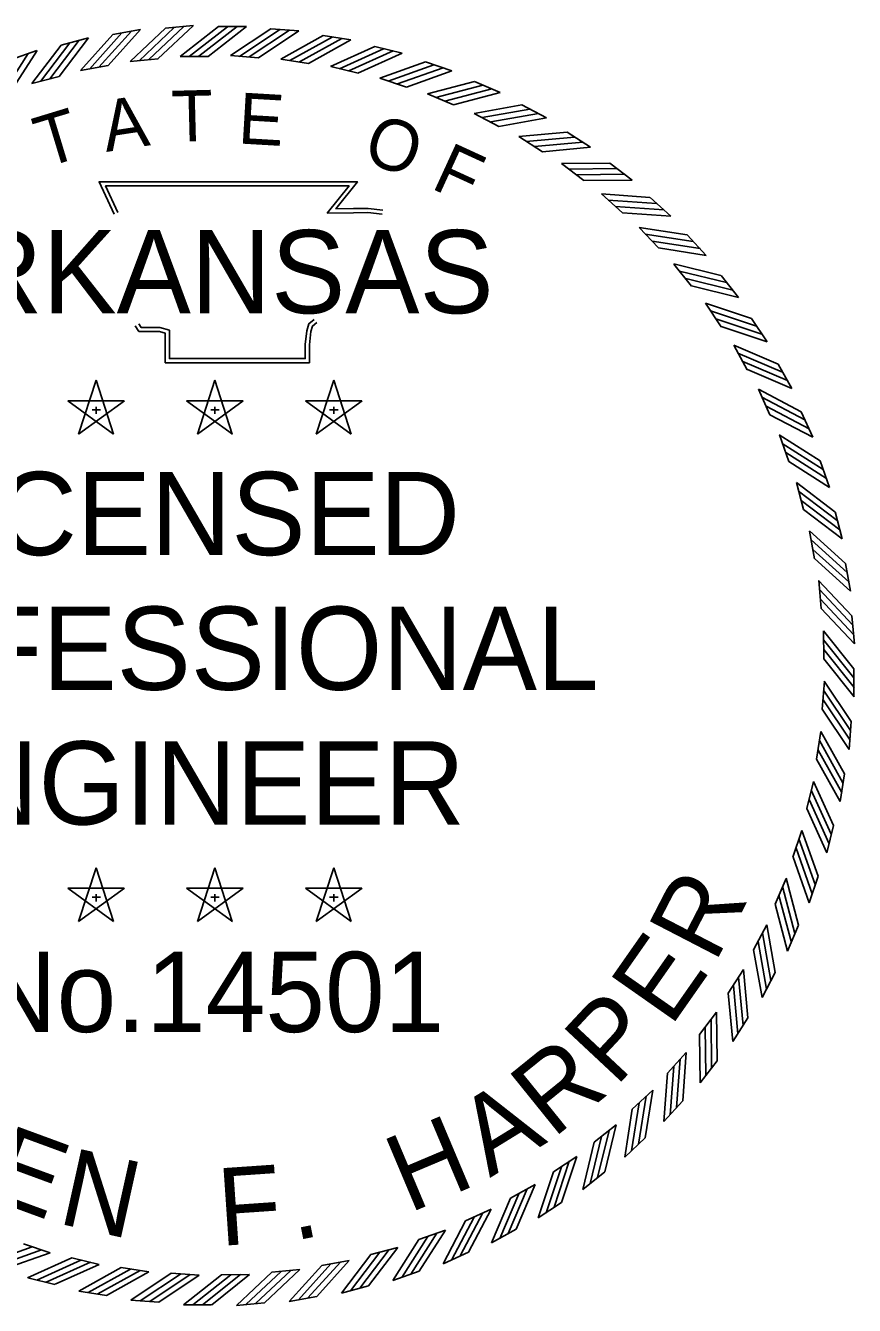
# Model space of a CAD drawing. Extents: x 16 to 1228740, y 11 to 152440.
# Drawn here: x 17.7445 to 17.8561, y 10.8148 to 10.987 of the extents above; entities that cross this region are included whole.
import ezdxf

# ---------------------------------------------------------------- set-up
doc = ezdxf.new("R2010")
doc.units = 0
doc.layers.add('STAMP_FRED', color=7, linetype='Continuous')

msp = doc.modelspace()

# ---------------------------------------------------------------- linework, layer by layer
at = {"layer": 'STAMP_FRED'}
for p, q in [((17.75631, 10.98579), (17.76003, 10.98645)), ((17.76337, 10.98663), (17.76712, 10.98698)), ((17.77051, 10.98684), (17.77428, 10.98684)), ((17.77757, 10.98656), (17.78133, 10.98629)), ((17.74935, 10.98437), (17.753, 10.98533)), ((17.78462, 10.98565), (17.78834, 10.98506)), ((17.74253, 10.98238), (17.74608, 10.98363)), ((17.76536, 10.98283), (17.76914, 10.98283)), ((17.77214, 10.98294), (17.77591, 10.98266)), ((17.79156, 10.98415), (17.79523, 10.98326)), ((17.75194, 10.98095), (17.75566, 10.9816)), ((17.75861, 10.98217), (17.76238, 10.98251)), ((17.77891, 10.98248), (17.78264, 10.9819)), ((17.78562, 10.98147), (17.78929, 10.98058)), ((17.79836, 10.98209), (17.80194, 10.9809)), ((17.7454, 10.97918), (17.74905, 10.98014)), ((17.79222, 10.97991), (17.7958, 10.97872)), ((17.80497, 10.97947), (17.80844, 10.97799)), ((17.79866, 10.97781), (17.80214, 10.97632)), ((17.81134, 10.97632), (17.81467, 10.97456)), ((17.80492, 10.97518), (17.80825, 10.97341)), ((17.81742, 10.97265), (17.8206, 10.97062)), ((17.81093, 10.97205), (17.81411, 10.97001)), ((17.81666, 10.96843), (17.81967, 10.96613)), ((17.82319, 10.96849), (17.82618, 10.96621)), ((17.82208, 10.96435), (17.82488, 10.96181)), ((17.82859, 10.96387), (17.83138, 10.96135)), ((17.82714, 10.95983), (17.82972, 10.95707)), ((17.83359, 10.95882), (17.83616, 10.95607)), ((17.83181, 10.95491), (17.83416, 10.95195)), ((17.83815, 10.95338), (17.84049, 10.95042)), ((17.83606, 10.94963), (17.83815, 10.94648)), ((17.84225, 10.94757), (17.84434, 10.94444)), ((17.83986, 10.94401), (17.84168, 10.9407)), ((17.84586, 10.94145), (17.84768, 10.93815)), ((17.75403, 10.93928), (17.75168, 10.93204)), ((17.75638, 10.93205), (17.75404, 10.93929)), ((17.77002, 10.93928), (17.76767, 10.93204)), ((17.77237, 10.93205), (17.77003, 10.93929)), ((17.78602, 10.93928), (17.78366, 10.93204)), ((17.78836, 10.93205), (17.78602, 10.93929)), ((17.84318, 10.9381), (17.84473, 10.93465)), ((17.75784, 10.93652), (17.75023, 10.93653)), ((17.75023, 10.93652), (17.75638, 10.93204)), ((17.75168, 10.93205), (17.75785, 10.93652)), ((17.77383, 10.93652), (17.76622, 10.93653)), ((17.76622, 10.93652), (17.77238, 10.93204)), ((17.76767, 10.93205), (17.77384, 10.93652)), ((17.78982, 10.93652), (17.78221, 10.93653)), ((17.78221, 10.93652), (17.78837, 10.93204)), ((17.78367, 10.93205), (17.78983, 10.93652)), ((17.75349, 10.9353), (17.75462, 10.9353)), ((17.75404, 10.93571), (17.75404, 10.93475)), ((17.76948, 10.9353), (17.77061, 10.9353)), ((17.77003, 10.93571), (17.77003, 10.93475)), ((17.78547, 10.9353), (17.7866, 10.9353)), ((17.78602, 10.93571), (17.78602, 10.93475)), ((17.84894, 10.93505), (17.85049, 10.93161)), ((17.846, 10.93193), (17.84726, 10.92837)), ((17.85149, 10.92842), (17.85275, 10.92486)), ((17.8483, 10.92555), (17.84926, 10.92189)), ((17.85349, 10.92159), (17.85445, 10.91795)), ((17.85007, 10.919), (17.85072, 10.91528)), ((17.85491, 10.91463), (17.85556, 10.91092)), ((17.85129, 10.91233), (17.85163, 10.90857)), ((17.85575, 10.90758), (17.8561, 10.90382)), ((17.85195, 10.90558), (17.85199, 10.9018)), ((17.85601, 10.90047), (17.85604, 10.8967)), ((17.85206, 10.8988), (17.85178, 10.89503)), ((17.85568, 10.89338), (17.8554, 10.88962)), ((17.8516, 10.89203), (17.85102, 10.8883)), ((17.85477, 10.88633), (17.85418, 10.88261)), ((17.85059, 10.88533), (17.8497, 10.88166)), ((17.85327, 10.87938), (17.85238, 10.87572)), ((17.84903, 10.87873), (17.84783, 10.87514)), ((17.75403, 10.87372), (17.75168, 10.86648)), ((17.75638, 10.86648), (17.75404, 10.87372)), ((17.77002, 10.87372), (17.76767, 10.86648)), ((17.77237, 10.86648), (17.77003, 10.87372)), ((17.78602, 10.87372), (17.78366, 10.86648)), ((17.78836, 10.86648), (17.78602, 10.87372)), ((17.85121, 10.87258), (17.85002, 10.869)), ((17.75784, 10.87095), (17.75023, 10.87096)), ((17.75023, 10.87095), (17.75638, 10.86647)), ((17.75168, 10.86648), (17.75785, 10.87095)), ((17.77383, 10.87095), (17.76622, 10.87096)), ((17.76622, 10.87095), (17.77238, 10.86647)), ((17.76767, 10.86648), (17.77384, 10.87095)), ((17.78982, 10.87095), (17.78221, 10.87096)), ((17.78221, 10.87095), (17.78837, 10.86647)), ((17.78367, 10.86648), (17.78983, 10.87095)), ((17.84693, 10.87228), (17.84544, 10.86881)), ((17.75349, 10.86974), (17.75462, 10.86974)), ((17.75404, 10.87014), (17.75404, 10.86919)), ((17.76948, 10.86974), (17.77061, 10.86974)), ((17.77003, 10.87014), (17.77003, 10.86919)), ((17.78547, 10.86974), (17.7866, 10.86974)), ((17.78602, 10.87014), (17.78602, 10.86919)), ((17.8443, 10.86603), (17.84253, 10.86269)), ((17.84859, 10.86597), (17.84711, 10.86251)), ((17.84117, 10.86002), (17.83913, 10.85683)), ((17.84544, 10.85961), (17.84368, 10.85627)), ((17.83755, 10.85428), (17.83525, 10.85128)), ((17.84177, 10.85352), (17.83974, 10.85035)), ((17.83346, 10.84887), (17.83093, 10.84606)), ((17.83761, 10.84776), (17.83532, 10.84476)), ((17.82895, 10.8438), (17.82619, 10.84122)), ((17.83299, 10.84236), (17.83046, 10.83956)), ((17.82403, 10.83913), (17.82107, 10.83679)), ((17.82794, 10.83736), (17.82519, 10.83478)), ((17.81875, 10.83489), (17.8156, 10.83279)), ((17.82249, 10.83279), (17.81954, 10.83045)), ((17.81313, 10.83109), (17.80982, 10.82926)), ((17.80721, 10.82777), (17.80377, 10.82622)), ((17.81669, 10.82869), (17.81355, 10.8266)), ((17.80105, 10.82495), (17.79748, 10.82369)), ((17.81057, 10.82509), (17.80727, 10.82326)), ((17.74785, 10.82192), (17.74426, 10.82311)), ((17.79467, 10.82265), (17.79101, 10.82168)), ((17.75445, 10.82035), (17.75078, 10.82125)), ((17.78812, 10.82088), (17.7844, 10.82022)), ((17.80417, 10.822), (17.80073, 10.82045)), ((17.76115, 10.81934), (17.75742, 10.81993)), ((17.76792, 10.81889), (17.76415, 10.81917)), ((17.78145, 10.81966), (17.77769, 10.81931)), ((17.79753, 10.81945), (17.79398, 10.81819)), ((17.7485, 10.81767), (17.74484, 10.81857)), ((17.7747, 10.81899), (17.77092, 10.81896)), ((17.79071, 10.81746), (17.78707, 10.8165)), ((17.75545, 10.81618), (17.75172, 10.81677)), ((17.78375, 10.81604), (17.78004, 10.81538)), ((17.76249, 10.81526), (17.75873, 10.81554)), ((17.76959, 10.81493), (17.76582, 10.8149)), ((17.77669, 10.81519), (17.77294, 10.81485))]:
    msp.add_line(p, q, dxfattribs=at)
for points in [[(17.75314, 10.98114), (17.7575, 10.98599)], [(17.75442, 10.9814), (17.75879, 10.98624)], [(17.75566, 10.98161), (17.76003, 10.98645)], [(17.75861, 10.98216), (17.76336, 10.98663)], [(17.75982, 10.98226), (17.76457, 10.98673)], [(17.76112, 10.98241), (17.76587, 10.98688)], [(17.76237, 10.98252), (17.76713, 10.98698)], [(17.76536, 10.98283), (17.7705, 10.98684)], [(17.76657, 10.98282), (17.77172, 10.98683)], [(17.76788, 10.98285), (17.77302, 10.98686)], [(17.76914, 10.98284), (17.77428, 10.98685)], [(17.77214, 10.98294), (17.77756, 10.98656)], [(17.77335, 10.98284), (17.77877, 10.98646)], [(17.77466, 10.98277), (17.78008, 10.98639)], [(17.77591, 10.98266), (17.78133, 10.98629)], [(17.74539, 10.97918), (17.74935, 10.98436)], [(17.74657, 10.97947), (17.75052, 10.98466)], [(17.74783, 10.97983), (17.75178, 10.98502)], [(17.74905, 10.98014), (17.753, 10.98533)], [(17.75194, 10.98094), (17.75631, 10.98579)], [(17.77891, 10.98248), (17.78461, 10.98564)], [(17.7801, 10.98228), (17.78581, 10.98544)], [(17.7814, 10.98211), (17.78711, 10.98527)], [(17.78264, 10.9819), (17.78834, 10.98506)], [(17.74139, 10.97773), (17.7449, 10.98323)], [(17.74257, 10.97814), (17.74609, 10.98364)], [(17.78561, 10.98147), (17.79156, 10.98415)], [(17.78679, 10.98117), (17.79273, 10.98385)], [(17.78807, 10.98089), (17.79401, 10.98357)], [(17.78928, 10.98058), (17.79523, 10.98326)], [(17.79221, 10.97991), (17.79836, 10.98209)], [(17.79336, 10.97951), (17.79951, 10.9817)], [(17.79461, 10.97913), (17.80076, 10.98131)], [(17.7958, 10.97872), (17.80194, 10.9809)], [(17.79866, 10.97781), (17.80496, 10.97947)], [(17.79977, 10.97732), (17.80608, 10.97899)], [(17.80098, 10.97683), (17.80729, 10.9785)], [(17.80213, 10.97633), (17.80844, 10.97799)], [(17.80491, 10.97518), (17.81133, 10.97632)], [(17.80598, 10.9746), (17.8124, 10.97574)], [(17.80715, 10.97402), (17.81357, 10.97516)], [(17.80825, 10.97342), (17.81467, 10.97456)], [(17.81092, 10.97205), (17.81742, 10.97265)], [(17.81194, 10.97138), (17.81843, 10.97199)], [(17.81306, 10.9707), (17.81955, 10.97131)], [(17.81411, 10.97001), (17.8206, 10.97062)], [(17.81666, 10.96843), (17.82318, 10.96849)], [(17.81762, 10.96768), (17.82414, 10.96775)], [(17.75646, 10.96161), (17.75445, 10.96597), (17.78922, 10.96599), (17.78632, 10.96234), (17.78868, 10.96237), (17.79065, 10.96239), (17.79262, 10.96218)], [(17.75696, 10.96184), (17.75531, 10.96542), (17.78808, 10.96543), (17.78516, 10.96177), (17.78868, 10.96182), (17.79062, 10.96184), (17.79256, 10.96163)], [(17.81867, 10.96691), (17.8252, 10.96698)], [(17.81966, 10.96614), (17.82619, 10.96621)], [(17.82207, 10.96435), (17.82858, 10.96387)], [(17.82297, 10.96352), (17.82947, 10.96305)], [(17.82396, 10.96267), (17.83046, 10.9622)], [(17.82488, 10.96182), (17.83139, 10.96134)], [(17.82713, 10.95983), (17.83358, 10.95882)], [(17.82796, 10.95894), (17.8344, 10.95793)], [(17.82887, 10.958), (17.83532, 10.957)], [(17.82972, 10.95708), (17.83617, 10.95607)], [(17.8318, 10.95492), (17.83814, 10.95338)], [(17.83255, 10.95396), (17.83889, 10.95242)], [(17.83339, 10.95295), (17.83973, 10.95141)], [(17.83416, 10.95196), (17.8405, 10.95042)], [(17.83605, 10.94963), (17.84224, 10.94757)], [(17.83672, 10.94861), (17.84291, 10.94656)], [(17.78374, 10.94704), (17.78315, 10.94656), (17.78295, 10.94584), (17.78276, 10.94404), (17.78276, 10.94163), (17.76335, 10.94163), (17.76335, 10.94488), (17.76335, 10.9456), (17.76256, 10.94584), (17.7598, 10.94584), (17.75931, 10.94659)], [(17.78339, 10.94747), (17.78266, 10.94688), (17.78241, 10.94594), (17.7822, 10.94407), (17.7822, 10.94219), (17.7639, 10.94219), (17.7639, 10.94488), (17.7639, 10.94601), (17.76264, 10.94639), (17.7601, 10.94639), (17.75977, 10.94689)], [(17.83747, 10.94754), (17.84366, 10.94549)], [(17.83815, 10.94649), (17.84435, 10.94443)], [(17.83985, 10.94401), (17.84585, 10.94145)], [(17.84043, 10.94294), (17.84643, 10.94038)], [(17.84109, 10.94181), (17.84709, 10.93925)], [(17.84169, 10.94071), (17.84769, 10.93815)], [(17.84317, 10.9381), (17.84894, 10.93505)], [(17.84366, 10.93699), (17.84943, 10.93394)], [(17.84422, 10.9358), (17.84999, 10.93276)], [(17.84473, 10.93465), (17.85049, 10.93161)], [(17.84599, 10.93193), (17.85149, 10.92842)], [(17.84639, 10.93078), (17.85188, 10.92727)], [(17.84685, 10.92956), (17.85235, 10.92605)], [(17.84726, 10.92837), (17.85275, 10.92486)], [(17.84829, 10.92555), (17.85348, 10.9216)], [(17.84859, 10.92438), (17.85378, 10.92042)], [(17.84895, 10.92312), (17.85414, 10.91916)], [(17.84926, 10.9219), (17.85445, 10.91795)], [(17.85006, 10.91901), (17.85491, 10.91464)], [(17.85026, 10.91781), (17.85511, 10.91344)], [(17.85052, 10.91652), (17.85536, 10.91216)], [(17.85072, 10.91529), (17.85557, 10.91092)], [(17.85128, 10.91234), (17.85575, 10.90758)], [(17.85138, 10.91113), (17.85585, 10.90637)], [(17.85153, 10.90982), (17.856, 10.90507)], [(17.85164, 10.90857), (17.8561, 10.90382)], [(17.85195, 10.90559), (17.85601, 10.90048)], [(17.85195, 10.90437), (17.85601, 10.89927)], [(17.85199, 10.90306), (17.85605, 10.89796)], [(17.85199, 10.90181), (17.85605, 10.8967)], [(17.85205, 10.89881), (17.85568, 10.89338)], [(17.85195, 10.8976), (17.85558, 10.89217)], [(17.85178, 10.89504), (17.85541, 10.88961)], [(17.85189, 10.89629), (17.85551, 10.89086)], [(17.8516, 10.89204), (17.85476, 10.88633)], [(17.8514, 10.89084), (17.85456, 10.88514)], [(17.85102, 10.88831), (17.85418, 10.8826)], [(17.85123, 10.88954), (17.85439, 10.88384)], [(17.85059, 10.88533), (17.85327, 10.87939)], [(17.85001, 10.88288), (17.85269, 10.87693)], [(17.85029, 10.88416), (17.85297, 10.87821)], [(17.8497, 10.88166), (17.85238, 10.87571)], [(17.84863, 10.87759), (17.85081, 10.87144)], [(17.84903, 10.87873), (17.85121, 10.87259)], [(17.84825, 10.87634), (17.85043, 10.87019)], [(17.84784, 10.87515), (17.85002, 10.869)], [(17.84644, 10.87118), (17.8481, 10.86487)], [(17.84693, 10.87229), (17.84859, 10.86598)], [(17.84595, 10.86996), (17.84762, 10.86365)], [(17.84545, 10.86881), (17.84711, 10.8625)], [(17.8443, 10.86604), (17.84544, 10.85961)], [(17.84313, 10.8638), (17.84427, 10.85737)], [(17.84372, 10.86497), (17.84486, 10.85855)], [(17.84254, 10.86269), (17.84368, 10.85627)], [(17.8405, 10.85901), (17.84111, 10.85251)], [(17.84117, 10.86002), (17.84177, 10.85353)], [(17.83982, 10.85789), (17.84042, 10.85139)], [(17.83913, 10.85684), (17.83974, 10.85034)], [(17.83755, 10.85429), (17.83761, 10.84776)], [(17.83603, 10.85227), (17.83609, 10.84575)], [(17.8368, 10.85333), (17.83687, 10.84681)], [(17.83526, 10.85128), (17.83532, 10.84476)], [(17.83346, 10.84887), (17.83299, 10.84237)], [(17.83179, 10.84699), (17.83131, 10.84048)], [(17.83264, 10.84798), (17.83217, 10.84147)], [(17.83094, 10.84606), (17.83046, 10.83956)], [(17.82895, 10.84381), (17.82794, 10.83737)], [(17.82712, 10.84207), (17.82611, 10.83563)], [(17.82806, 10.84299), (17.82705, 10.83654)], [(17.8262, 10.84122), (17.82519, 10.83478)], [(17.82308, 10.83839), (17.82154, 10.83206)], [(17.82403, 10.83914), (17.8225, 10.8328)], [(17.82108, 10.83679), (17.81954, 10.83045)], [(17.82207, 10.83756), (17.82053, 10.83122)], [(17.81875, 10.83489), (17.81669, 10.8287)], [(17.81561, 10.83279), (17.81355, 10.8266)], [(17.81666, 10.83348), (17.8146, 10.82729)], [(17.81773, 10.83423), (17.81568, 10.82804)], [(17.81313, 10.83109), (17.81057, 10.82509)], [(17.81093, 10.82986), (17.80837, 10.82386)], [(17.81206, 10.83052), (17.8095, 10.82452)], [(17.80722, 10.82777), (17.80417, 10.82201)], [(17.80983, 10.82926), (17.80727, 10.82326)], [(17.80377, 10.82622), (17.80073, 10.82045)], [(17.80492, 10.82672), (17.80188, 10.82095)], [(17.80611, 10.82729), (17.80306, 10.82152)], [(17.7999, 10.82456), (17.79639, 10.81906)], [(17.80105, 10.82495), (17.79754, 10.81946)], [(17.74545, 10.8227), (17.73931, 10.82052)], [(17.79467, 10.82265), (17.79072, 10.81746)], [(17.79749, 10.82369), (17.79398, 10.81819)], [(17.79868, 10.82409), (17.79517, 10.8186)], [(17.74671, 10.82231), (17.74056, 10.82013)], [(17.74785, 10.82192), (17.74171, 10.81974)], [(17.75078, 10.82124), (17.74483, 10.81856)], [(17.752, 10.82094), (17.74605, 10.81825)], [(17.78812, 10.82088), (17.78376, 10.81604)], [(17.79102, 10.82168), (17.78706, 10.8165)], [(17.79224, 10.82199), (17.78828, 10.8168)], [(17.79349, 10.82235), (17.78954, 10.81716)], [(17.75328, 10.82065), (17.74733, 10.81797)], [(17.75445, 10.82036), (17.74851, 10.81768)], [(17.75742, 10.81993), (17.75172, 10.81676)], [(17.75866, 10.81972), (17.75296, 10.81656)], [(17.75996, 10.81954), (17.75426, 10.81638)], [(17.76116, 10.81935), (17.75545, 10.81618)], [(17.76416, 10.81916), (17.75873, 10.81554)], [(17.76541, 10.81906), (17.75998, 10.81544)], [(17.77769, 10.81931), (17.77294, 10.81484)], [(17.77894, 10.81941), (17.77419, 10.81495)], [(17.78024, 10.81956), (17.77549, 10.8151)], [(17.78145, 10.81966), (17.7767, 10.8152)], [(17.7844, 10.82022), (17.78004, 10.81538)], [(17.78564, 10.82043), (17.78127, 10.81558)], [(17.78693, 10.82068), (17.78256, 10.81584)], [(17.76671, 10.81899), (17.76129, 10.81537)], [(17.76792, 10.81889), (17.7625, 10.81527)], [(17.77093, 10.81896), (17.76582, 10.8149)], [(17.77218, 10.81896), (17.76708, 10.8149)], [(17.77349, 10.819), (17.76838, 10.81494)], [(17.7747, 10.819), (17.7696, 10.81494)]]:
    msp.add_lwpolyline(points, dxfattribs=at)

# ---------------------------------------------------------------- texts
for s, height, rotation, p in [('T', 0.00686, 1.4789, (17.76426, 10.97135)), ('E', 0.00686, 356.672, (17.77304, 10.97114)), ('T', 0.00686, 16.9015, (17.74707, 10.96781)), ('A', 0.00686, 8.6788, (17.7554, 10.96998)), ('O', 0.00686, 341.2218, (17.78969, 10.96879)), ('F', 0.00686, 335.3628, (17.79893, 10.96517)), ('R', 0.01042, 62.6418, (17.83731, 10.8607)), ('E', 0.01042, 54.981, (17.83135, 10.85214)), ('P', 0.01042, 46.9554, (17.82395, 10.8441)), ('R', 0.01042, 38.9298, (17.81549, 10.83718)), ('A', 0.01042, 31.6338, (17.80703, 10.83197)), ('H', 0.01042, 22.8786, (17.79612, 10.8272)), ('E', 0.01042, 339.8321, (17.73888, 10.82949)), ('N', 0.01042, 347.4929, (17.74868, 10.82592)), ('F', 0.01042, 3.9089, (17.77076, 10.82284)), ('.', 0.01042, 11.205, (17.78067, 10.82352))]:
    msp.add_text(s, height=height, rotation=rotation, dxfattribs=at).set_placement(p)
for s, height, p in [('ARKANSAS', 0.011193, (17.72603, 10.94829)), ('LICENSED', 0.011193, (17.72816, 10.91576)), ('PROFESSIONAL', 0.0111934, (17.70524, 10.89764)), ('ENGINEER', 0.011193, (17.7255, 10.87952)), ('No.14501', 0.010794, (17.7383, 10.85161))]:
    msp.add_text(s, height=height, dxfattribs=at).set_placement(p)

doc.saveas('drawing.dxf')
